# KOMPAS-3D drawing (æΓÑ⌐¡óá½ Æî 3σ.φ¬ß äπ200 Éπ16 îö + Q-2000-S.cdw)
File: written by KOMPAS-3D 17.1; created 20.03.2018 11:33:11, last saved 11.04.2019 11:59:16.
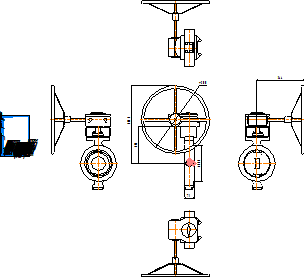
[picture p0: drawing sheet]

Sheet 1: A4, portrait

Title block, sheet 1: name: Стейнвал ТМ 3х.экс / Ду200 Ру16 МФ + Q-2000-S; material: Внимание! Данный продукт является объектом авторского права ООО «Торговый Дом АДЛ». / Запрещается изменение, копирование, распространение / (в том числе путем копирования на другие сайты и ресурсы в Интернете) / или любое иное использование информации и объектов без предварительного / согласия правообладателя (ООО «Торговый Дом АДЛ»).; mass: 97,3; sheets: 1; organisation: ООО "Торговый дом АДЛ"; sheet format: A4; stored path: \\adlc.lan\data\АДЛ_ПКД\3D-модели\ADL production\Дисковые поворотные затворы СТЕЙНВАЛ\Трехэксцентриковый\Стейнвал м-ф\С редуктором\KOMPAS 2D\Стейнвал ТМ 3х.экс Ду200 Ру16 МФ + Q-2000-S.cdw

Views: Вид 1, Проекционный вид 2, Проекционный вид 4, Проекционный вид 5
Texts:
  kka
  adl
Dimensions and other numbers on the sheet: 71; 270; 569,5; 268; 500; 344; 1:1; 1; 97,3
